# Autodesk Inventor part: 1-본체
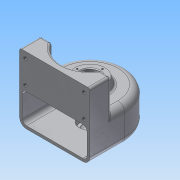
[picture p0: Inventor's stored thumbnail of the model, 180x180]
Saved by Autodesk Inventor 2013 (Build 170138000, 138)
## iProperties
Created: 2015-02
Part Number: 1-본체
Material: 알루미늄 6061
Document SubType Name: Modeling
Designer: Administrator
Density: 2.40731 g/cm^3
Mass: 511.46 g
Surface Area: 707.565 cm^2
Volume: 212.461 cm^3
Author: Administrator
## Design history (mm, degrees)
sketch "스케치1"
  geometry: L1 (-50, 0)-(-50, -50); L2 (-50, -50)-(50, -50); L3 (50, -50)-(50, 0); A1 r 50 centre (0, 0) between (-50, 0) and (50, 0); 1 further point
  constraints: 6 end point, 2 point on circle, 2 tangent, 2 vertical, 1 centre point, 1 coincident, 1 perpendicular
  dimensions: "d0" = 50 radius of A1; "d2" = 50 distance from line of L2 point (0, 0)
extrude "돌출1" new body sketch "스케치1" stored distance "d3" = 50; taper "d4" = 0 deg
sketch "스케치2"
  geometry: L1 (-50, 0)-(-50, -50) reference; L2 (-50, -50)-(50, -50) reference; L3 (50, -50)-(50, 0) reference; L4 (-50, -20)-(-34.641, -20); L5 (34.641, -20)-(50, -20); A1 r 50 centre (0, 0) between (50, 0) and (-50, 0) reference; A2 r 40 centre (0, 0) between (-34.641, -20) and (34.641, -20)
  constraints: 4 end point, 2 collinear, 2 point on circle, 2 point on line, 1 centre point, 1 coincident, 1 perpendicular
  dimensions: "d5" = 40 radius of A2; "d7" = 30 distance between parallel lines of L2 L5
extrude "돌출2" join sketch "스케치2" distance "d8" = 45; taper "d9" = 0 deg
node "작업 평면1"
sketch "스케치3"
  geometry: L1 (-50, 0)-(-50, -50) reference; L2 (50, -50)-(50, 0) reference; L3 (-50, -50)-(50, -50) reference; L4 (46, 0)-(46, -50); L5 (-46, -50)-(-46, 0); L6 (-46, -50)-(46, -50); A1 r 50 centre (0, 0) between (50, 0) and (-50, 0) reference; A2 r 46 centre (0, 0) between (46, 0) and (-46, 0); 1 further point
  constraints: 6 end point, 2 point on circle, 2 point on line, 1 centre point, 1 collinear
  dimensions: "d11" = 4 radial gap between concentric circles of A1 A2; "d12" = 4 distance between parallel lines of L1 L5; "d13" = 4 distance between parallel lines of L2 L4
extrude "돌출3" cut sketch "스케치3" distance "d14" = 42; taper "d15" = 0 deg
sketch "스케치4"
  geometry: C1 r 25 at (0, 0); A1 r 40 centre (0, 0) between (-34.641, -20) and (34.641, -20) reference
  constraints: 1 centre point, 1 coincident
  dimensions: "d16" = 50 diameter of C1
extrude "돌출4" join sketch "스케치4" distance "d18" = 10; taper "d19" = -20 deg
sketch "스케치5"
  geometry: C1 r 20 at (0, 0); A1 r 50 centre (0, 0) between (50, 0) and (-50, 0) reference
  constraints: 1 centre point, 1 coincident
  dimensions: "d20" = 40 diameter of C1
extrude "돌출5" join sketch "스케치5" distance "d22" = 9; taper "d23" = 0 deg
sketch "스케치6"
  geometry: L1 (100, 0)-(100, 95) reference; L2 (0, 95)-(100, 95) reference; 5 further points
  constraints: 2 horizontal alignment, 2 vertical alignment
  dimensions: "d24" = 33 distance of point (91.75, 53) point (91.75, 86); "d26" = 9 distance from line of point (91.75, 86) L2; "d27" = 83.5 distance of point (91.75, 86) point (8.25, 86); "d28" = 8.25 distance from line of L1 point (91.75, 86)
hole "구멍1" sketch "스케치6" at (8.25, 86), (8.25, 53), (91.75, 86), (91.75, 53) diameter "d29" = 5.134; stored, may be unused: countersink angle "d33" = 90 deg, drill point angle "d35" = 118 deg; dims "d30" = 10, "d31" = 4, "d32" = 2, "d34" = 13
hole "구멍2" diameter "d38" = 20; stored, may be unused: countersink angle "d42" = 90 deg, drill point angle "d44" = 0 deg; dims "d36" = 10, "d37" = 10, "d39" = 10, "d40" = 28, "d41" = 10, "d43" = 14
hole "구멍3" diameter "d47" = 20; stored, may be unused: countersink angle "d51" = 90 deg, drill point angle "d53" = 0 deg; dims "d45" = 10, "d46" = 10, "d48" = 10, "d49" = 28, "d50" = 8, "d52" = 10
sketch "스케치7"
  geometry: L1 (0, 18)-(-18, 0); L2 (-18, 0)-(0, -18); L3 (0, -18)-(18, 0); L4 (18, 0)-(0, 18); C1 r 14 at (0, 0) reference; 4 further points
  constraints: 8 end point, 4 coincident, 2 horizontal alignment, 2 parallel, 2 vertical alignment, 1 perpendicular
  dimensions: "d54" = 36 distance of L3.end L1.end
hole "구멍4" sketch "스케치7" at (0, 18), (18, 0), (0, -18), (-18, 0) diameter "d56" = 2.459; stored, may be unused: countersink angle "d60" = 90 deg, drill point angle "d62" = 118 deg; dims "d57" = 6, "d58" = 28, "d59" = 8, "d61" = 9
node "작업 평면2"
sketch "스케치8"
  geometry: L1 (-50, -25)-(50, -25) reference; 2 further points
  constraints: 1 coincident, 1 other
  dimensions: "d63" = 25 distance from line of point (0, 0) L1
feature "엠보싱1" sketch "스케치8" dims "d64" = 0.5, "d65" = 0
fillet "모깎기1" dims "d66" = 10, "d67" = 6, "d68" = 0.3
fillet "모깎기2" dims "d69" = 3
fillet "모깎기3" dims "d70" = 3
chamfer "모따기1" distance "d71" = 1; stored, may be unused: second distance "d72" = 2, angle "d73" = 45 deg
node "솔리드1"
other parameters: "d10" = -4
